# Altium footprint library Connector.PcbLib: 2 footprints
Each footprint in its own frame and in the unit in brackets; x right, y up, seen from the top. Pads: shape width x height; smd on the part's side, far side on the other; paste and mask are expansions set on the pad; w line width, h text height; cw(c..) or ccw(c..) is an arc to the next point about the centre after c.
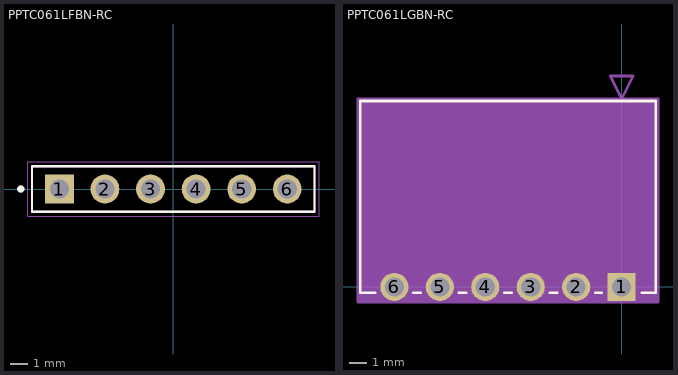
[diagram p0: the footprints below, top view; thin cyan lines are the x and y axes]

## PPTC061LFBN-RC [mm] "6 Position Header Connector 0.100\" (2.54mm) Through Hole Tin"
height 8.5
pads (6):
  rect 1.605x1.605 / inner round 1.605 / far side rect 1.605x1.605 hole 1.07: 1(-6.35,0)
  round 1.605 hole 1.07: 2(-3.81,0) 3(-1.27,0) 4(1.27,0) 5(3.81,0) 6(6.35,0)
Top Overlay:
  circle w0.2: c-8.5,0 r0.1
  lines w0.127: -7.87,-1.27 7.87,-1.27 7.87,1.27 -7.87,1.27 -7.87,-1.27
Mechanical 13:
  circle w0.2: c-8.5,0 r0.1
  lines w0.127: -7.87,-1.27 7.87,-1.27 7.87,1.27 -7.87,1.27 -7.87,-1.27
Mechanical 15:
  lines w0.05: -8.12,-1.52 8.12,-1.52 8.12,1.52 -8.12,1.52 -8.12,-1.52
3D body "step_temp.STEP": height 8.51, standoff -3.2, extent -7.874,-1.27 7.874,1.27

## PPTC061LGBN-RC [mil] "6 Position Header Connector 0.100\" (2.54mm) Through Hole, Right Angle Tin"
pads (6):
  rect 62x62 hole 42 paste-99999 mask+0: 1(0,0)
  round 62 hole 42 paste-99999 mask+0: 2(-100,0) 3(-200,0) 4(-300,0) 5(-400,0) 6(-500,0)
Top Overlay:
  lines w6: -542.14,-13 -575,-13 -575,409 75,409 75,-13 44.1,-13 ; -457.86,-13 -442.14,-13 ; -357.86,-13 -342.14,-13 ; -257.86,-13 -242.14,-13 ; -157.86,-13 -142.14,-13 ; -57.86,-13 -44.1,-13
Mechanical 13:
  lines w1: -570,-8 70,-8 70,404 -570,404 -570,-8 ; -25,464 0,414 25,464 -25,464
  lines w6: -25,464 0,414 25,464 -25,464
Mechanical 15:
  region: 80,414 -580,414 -580,-33 80,-33
  lines w6: -580,-33 80,-33 80,414 -580,414 -580,-33
3D body "PPTC061LGBN-RC.STEP": height 100, standoff -124.02, extent -559.84,-7.87 59.84,397.64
